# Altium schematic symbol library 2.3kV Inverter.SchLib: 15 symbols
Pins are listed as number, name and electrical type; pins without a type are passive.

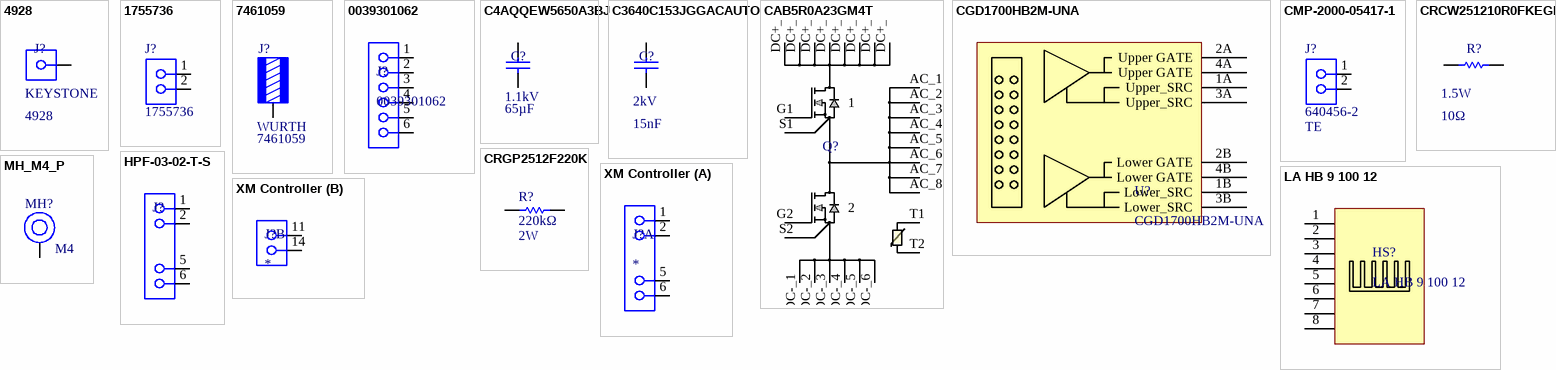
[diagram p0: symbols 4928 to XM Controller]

## 4928
designator J?  Manufacturer: KEYSTONE  (hidden comment: 4928)
QUICK FIT TERMINAL .240"
footprint KEYSTONE_4928
pins: 1,2,3

## 1755736
designator J?
Male Header, Pitch 5.08 mm, 1 x 2 Postion, Height 12 mm, Tail Length 3.9 mm, RoHS, Bulk; Manufacturer: Phoenix Contact; Content: 250pc(s); Pitch: 5.08mm; Industrial packaging: Yes; Number of contacts: 2
footprint 1755736 (THD, 2-Leads, Body 12.16x8.6mm, Pitch 5.08mm)
pins: 1, 2

## 7461059
designator J?  Manufacturer: WURTH  (hidden comment: 7461059)
TERM REDCUBE M6 16PIN PCB; NexarPartId: 75500417; Current Rating: 240A
footprint 7461059 (M6, thr 13.5mm)
pins: 1

## 0039301062
designator J?
CONN HEADER R/A 6POS 4.2MM; Manufacturer: MOLEX
footprint FP-39-30-1062-MFG
pins: 1, 2, 3, 4, 5, 6

## C4AQQEW5650A3BJ
designator C?  value 65µF  Voltage: 1.1kV  (hidden comment: C4AQQEW5650A3BJ)
CAP FILM 65UF 5% 1.1KVDC RAD; Manufacturer: KEMET
footprint C4AQNEW5650M3BJ
pins: 1A,1B 1, 2A,2B 2

## C3640C153JGGACAUTO
designator C?  value 15nF  Voltage: 2kV  (hidden comment: C3640C153JGGACAUTO)
CAP CER 0.015UF 2KV C0G/NP0 3640; Manufacturer: KEMET
footprint CAPC9501060_270N_KEM
footprint CAPC9501060_270N_KEM-L
footprint CAPC9501060_270N_KEM-M
pins: 1, 2

## CAB5R0A23GM4T
designator Q?  (value not drawn)
Manufacturer: WOLFSPEED
footprint CAB5R0A23GM4 (Wolfpack GM Half-Bridge 2.3kV footprint)
footprint CAB5R0A23GM4_NOHOLE (Wolfpack GM Half-Bridge 2.3kV footprint)
pins: AC_1, AC_2, AC_3, AC_4, AC_5, AC_6, AC_7, AC_8, DC+_1, DC+_2, DC+_3, DC+_4, DC+_5, DC+_6, DC+_7, DC+_8, DC-_1, DC-_2, DC-_3, DC-_4, DC-_5, DC-_6, G1, G2, S1, S2, T1 NTC1, T2

## CGD1700HB2M-UNA
designator U?
CONN HEADER SMD 4POS 2.54MM; Sub-part1: TSM-102-02-S-DV; Manufacturer: WOLFSPEED
footprint CGD1700HB2P-UNA (Wolfpack FM/GM Gate Driver)
footprint CGD1700HB2P-UNA_NOHOLE (Wolfpack FM/GM Gate Driver)
pins: 1A Upper_SRC, 1B Lower_SRC, 2A Upper GATE, 2B Lower GATE, 3A Upper_SRC, 3B Lower_SRC, 4A Upper GATE, 4B Lower GATE

## CMP-2000-05417-1
designator J?, comment 640456-2  Manufacturer Print: TE
Male Header, Pitch 2.54 mm, 1 x 2 Position, Height 10.49 mm, Tail Length 3.556 mm, -55 to 105 degC, RoHS, Bulk; Manufacturer: TE Connectivity; Standards: RoHSCompliant,ELVCompliant,UL94V-0; Material, Housing: Polyester; Agency Approvals: CSA,UL; Brand/Series: MTA-100Series; Contact Centerline Spacing: 0.100 / in.; Material, Contact: CopperAlloy; Current, Rating: 5 / A; Color, Housing: White; Contact Termination Area Plating: Tin; Special Features: Pinstrip; Number of Positions: 2; Pin Spacing: 0.1 / "; Temperature, Operating: -55to+105 / degC; Angle: Straight; Mount Angle: Vertical; Connector Type: MTA-100; Primary Type: InterconnectSystem; Voltage, Rating: 250 / V; Mounting Hole Size: 0.04 / "
footprint TECO-640456-2_V (HDR, 2-Leads, Body 5.715x5.08mm, Pitch 2.54mm)
pins: 1, 2

## CRCW251210R0FKEGHP
designator R?  value 10Ω  Power: 1.5W  (hidden comment: CRCW251210R0FKEGHP)
RES SMD 10 OHM 1% 1.5W 2512; Manufacturer: VISHAY DALE
footprint FP-RMCF2512-IPC_A
footprint FP-RMCF2512-IPC_B
footprint FP-RMCF2512-IPC_C
footprint FP-RMCF2512-MFG
pins: 1, 2

## CRGP2512F220K
designator R?  Resistance: 220kΩ  Power Rating: 2W  (hidden comment: CRGP2512F220K)
RES 220K OHM 1% 2W 2512; Manufacturer: TE; Value: 220kΩ; Temperature Coefficient: ±100ppm/°C; Tolerance: 0.01; Voltage Rating: 500V
footprint FP-CRGP2512-IPC_C
footprint FP-CRGP2512-IPC_A
footprint FP-CRGP2512-IPC_B
pins: 1, 2

## HPF-03-02-T-S
designator J?  (value not drawn)
CONN RCPT 3POS 0.2 TIN SMD
footprint SAMTEC_HPF-03-02-T-S
pins: 1, 2, 5, 6

## LA HB 9 100 12
designator HS?
HEATSINK EXTRUSION 100MM; Manufacturer: FISCHER
footprint LA HB 9 100
pins: 1, 2, 3, 4, 5, 6, 7, 8

## MH_M4_P
designator MH?  Size: M4  (hidden comment: *)
footprint MH_M4_P (M4 plated mounting hole)
pins: 1

## XM Controller
designator J?
footprint XM CONTROLLER
part A pins: 1, 2, 5, 6
part B pins: 11, 14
